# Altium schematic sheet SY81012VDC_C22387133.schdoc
size 127 x 101 mm
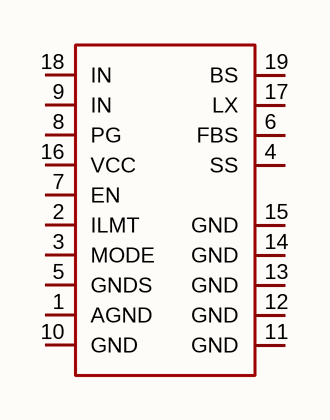
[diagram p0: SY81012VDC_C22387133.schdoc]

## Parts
U?  sy81012vdc_c22387133  [QFN-19_L4.0-W3.0-P0.5-TL]  (value not drawn)

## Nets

Not connected (* = marked no-connect by the designer): U? 1(AGND) 2(ILMT) 3(MODE) 4(SS) 5(GNDS) 6(FBS) 7(EN) 8(PG) 9(IN) 10(GND) 11(GND) 12(GND) 13(GND) 14(GND) 15(GND) 16(VCC) 17(LX) 18(IN) 19(BS)

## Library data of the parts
U? = sy81012vdc_c22387133: 功能类型:降压型;工作电压:2.7V~16V;输出电压:600mV~5.5V;输出电流:12A;输出类型:可调;; Manufacturer: Silergy(矽力杰); AddInBom: yes; ModelId: c2de26abb85e45b78bde1cd9ae083e8c; ModelTransform: 118.8974,158.267,0,0,0,0,0.002,-1.38,0; Function: 降压型; Output Current: 12A; Frequency - Switching: 600kHz~1MHz; Synchronous Rectifier: 是; Number of Outputs: 1; Topology: 降压式; Quiescent Current: 850uA; Switch tube (built-in/external): 内置; Output Type: 可调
